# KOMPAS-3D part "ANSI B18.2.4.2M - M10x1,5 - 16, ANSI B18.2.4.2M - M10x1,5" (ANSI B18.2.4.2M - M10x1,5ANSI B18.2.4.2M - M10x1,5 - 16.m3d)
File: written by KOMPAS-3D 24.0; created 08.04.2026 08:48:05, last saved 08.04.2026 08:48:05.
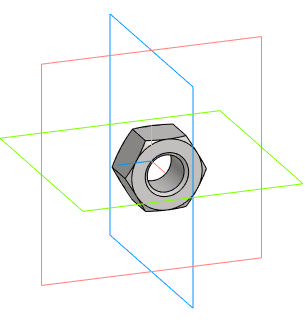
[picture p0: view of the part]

Document properties: Автор: Main; Полное имя файла: D:\DN.ru Аутсерс\Стекло смотровое DN.ru\Исходники\Стекло смотровое DN.ru SG2-34G-F тип В ГОСТ 21836-2021 Ду150 Ру16, углеродистая сталь, фланцевое\ANSI B18.2.4.2M - M10x1,5ANSI B18.2.4.2M - M10x1,5 - 16.m3d

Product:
- Body: Solid1  | qty 1
- Part/product: ANSI B18.2.4.2M - M10x1,5 - 16  | designation ANSI B18.2.4.2M - M10x1,5
    Комментарий: Типы метрических   шестигранных гаек   2
    additional columns: Сталь, мягкая

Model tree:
1. Solid1  (labels: Solid1)

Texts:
  ANSI B18.2.4.2M - M10x1,5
